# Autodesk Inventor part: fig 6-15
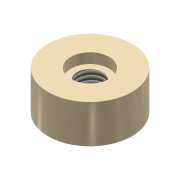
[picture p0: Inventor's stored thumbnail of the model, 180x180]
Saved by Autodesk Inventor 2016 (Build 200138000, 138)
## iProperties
Shininess: 65.0
Angle Display Precision: 2
Document Length Units: 11269
Document Angle Units: 11279
Document Time Units: 11290
Document Mass Units: 11283
Document Length Units Precision: 3
Document Angle Units Precision: 2
Created: 2001-11
Part Number: fig 6-15
Document SubType Name: Modeling
Designer: Renu Muthoo
Density: 1 g/cm^3
Material: Generic
Appearance: Metal-Titanium (Polished)
Density: 0.0
Volumn: 0.0
Area: 0.0
PropertySet Name: Model Information
Control State: 0
Master: False
Checked Out: False
Author: Renu Muthoo
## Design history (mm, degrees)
sketch "Sketch1"
  geometry: C1 r 16.401 at (0, 0)
  constraints: 1 centre point
extrude "Extrusion1" new body sketch "Sketch1" distance "d0" = 15; taper "d1" = 0 deg
hole "Hole3" diameter "d18" = 10.106; stored, may be unused: countersink angle "d22" = 90 deg, drill point angle "d24" = 118 deg; dims "d16" = 10, "d17" = 10, "d19" = 6, "d20" = 15, "d21" = 4, "d23" = 10
body "Solid1"
